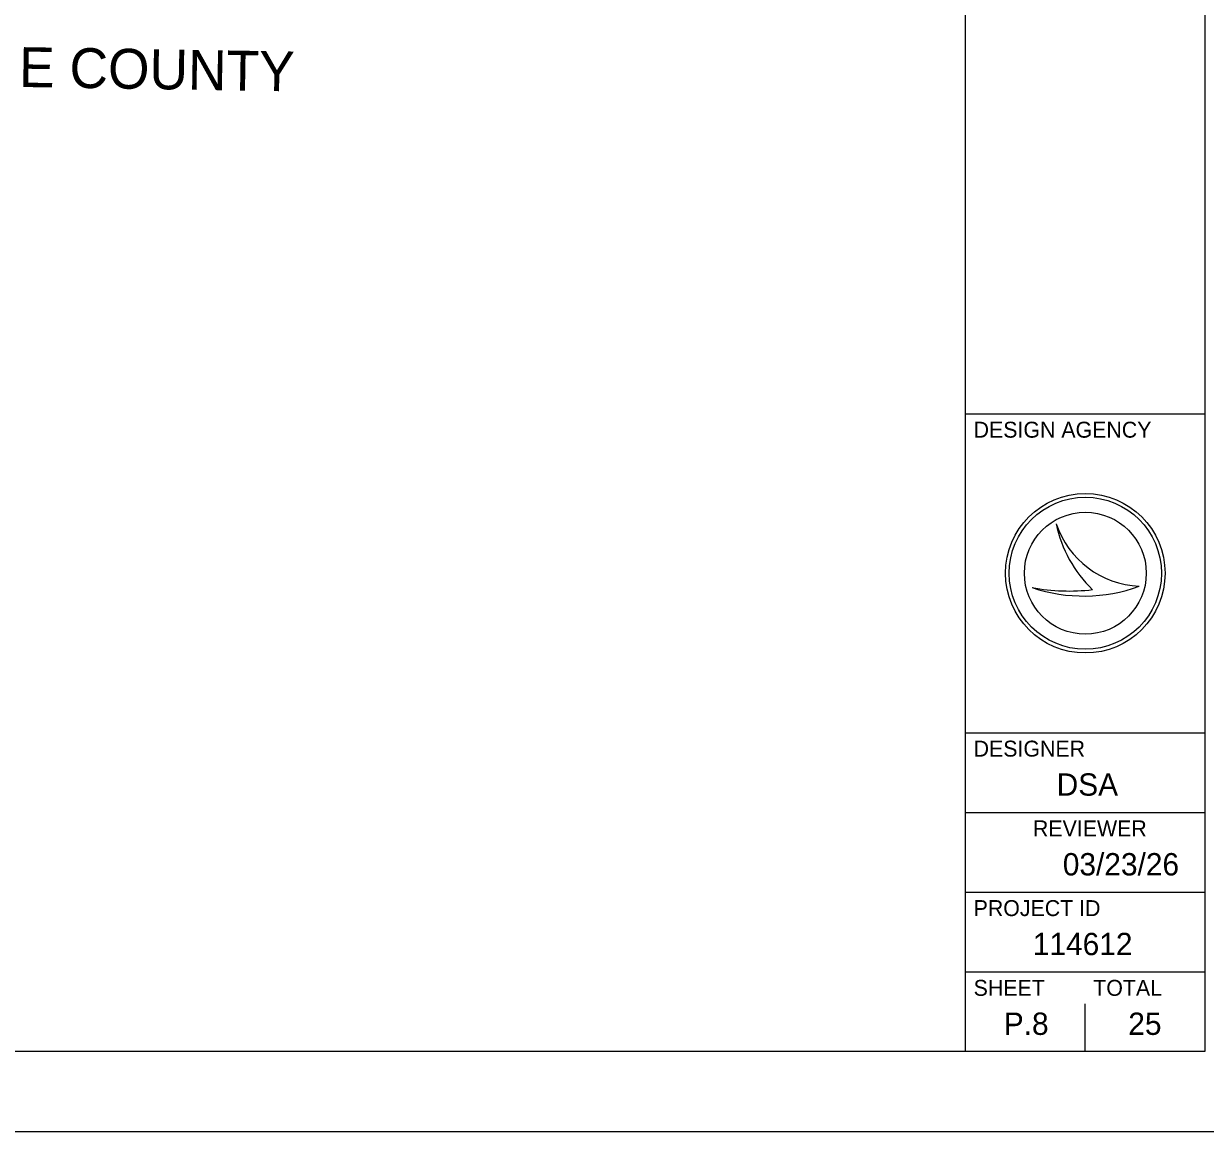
# Model space of a CAD drawing. Extents: x -82 to 873, y 0 to 440.
# Drawn here: x 521.9 to 670.1, y 0 to 138.9 of the extents above; entities that cross this region are included whole.
import ezdxf

# ---------------------------------------------------------------- set-up
doc = ezdxf.new("R2010")
doc.units = 0
for name, color, linetype in [('GM_X_Adjacent_County_Text', 7, 'Continuous'), ('SH_Border', 7, 'Continuous'), ('SH_Cut_Line', 7, 'Continuous'), ('SH_Data', 7, 'Continuous')]:
    doc.layers.add(name, color=color, linetype=linetype)

msp = doc.modelspace()

# ---------------------------------------------------------------- linework, layer by layer
at = {"layer": 'SH_Border'}
for p, q in [((640, 10), (640, 430)), ((640, 90), (670, 90)), ((640, 50), (670, 50)), ((640, 40), (670, 40)), ((640, 30), (670, 30)), ((640, 20), (670, 20))]:
    msp.add_line(p, q, dxfattribs=at)
msp.add_lwpolyline([(30, 430), (670, 430), (670, 10), (30, 10)], close=True, dxfattribs=at)
at = {"layer": 'SH_Cut_Line'}
msp.add_lwpolyline([(0, 0), (680, 0), (680, 440), (0, 440)], close=True, dxfattribs=at)
at = {"layer": 'SH_Data'}
for p, q in [((651.35, 76.19), (651.35, 76.19)), ((655, 70), (655, 70)), ((648.34, 68.19), (648.34, 68.19)), ((661.75, 68.37), (661.75, 68.37)), ((655, 10), (655, 16)), ((647.5, 13.5), (647.5, 13.5))]:
    msp.add_line(p, q, dxfattribs=at)
for radius in [10, 9.54, 9.54, 7.64]:
    msp.add_circle((655, 70), radius, dxfattribs=at)
for centre, radius, start, end in [((662.32, 79.95), 11.6, 198.9257, 198.9319), ((666.93, 79.4), 15.91, 191.6379, 191.6421), ((662.32, 79.95), 11.6, 198.9319, 267.1657), ((666.93, 79.4), 15.91, 191.6421, 226.0947), ((654.79, 87.4), 20.26, 251.4576, 290.0832), ((652.96, 93.09), 25.32, 259.4964, 259.4995), ((654.79, 87.4), 20.26, 251.4527, 251.4576), ((652.96, 93.09), 25.32, 259.4995, 276.6672)]:
    msp.add_arc(centre, radius, start, end, dxfattribs=at)

# ---------------------------------------------------------------- texts
at = {"layer": 'GM_X_Adjacent_County_Text'}
msp.add_text('ERIE COUNTY', height=5, rotation=359.0638, dxfattribs=at).set_placement((510.16, 131.17))
at = {"layer": 'SH_Data'}
for s, height, p in [('DESIGN AGENCY', 2, (641, 87)), ('DESIGNER', 2, (641, 47)), ('DSA', 2.8, (651.41, 42.1)), ('REVIEWER', 2, (648.44, 37)), ('03/23/26', 2.8, (652.18, 32.1)), ('PROJECT ID', 2, (641, 27)), ('114612', 2.8, (648.42, 22.1)), ('SHEET', 2, (641, 17)), ('TOTAL', 2, (656, 17)), ('P.8', 2.8, (644.78, 12.1)), ('25', 2.8, (660.39, 12.1))]:
    msp.add_text(s, height=height, dxfattribs=at).set_placement(p)

doc.saveas('drawing.dxf')
